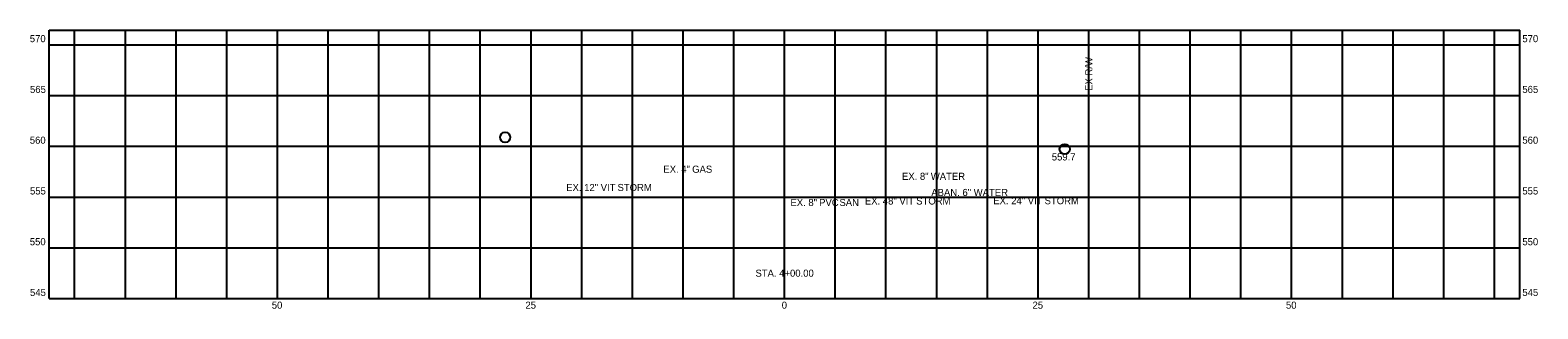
# Model space of a CAD drawing. Extents: x -74 to 74, y 544 to 571.
import ezdxf

# ---------------------------------------------------------------- set-up
doc = ezdxf.new("R2010")
doc.units = 0
for name, color, linetype in [('CM_Corridor_Key_Station', 7, 'Continuous'), ('CM_Corridor_Top_Mesh', 7, 'Continuous'), ('DT_P_Graded_Shoulder', 7, 'Continuous'), ('MD_P_GRADE_BREAK', 7, 'Continuous'), ('MD_P_Surface_Sidewalk', 7, 'Continuous'), ('MD_P_SW_BOT', 7, 'Continuous'), ('MD_P_SW_TOP', 7, 'Continuous'), ('PV_P_Walk', 7, 'Continuous')]:
    doc.layers.add(name, color=color, linetype=linetype)

msp = doc.modelspace()

# ---------------------------------------------------------------- linework, layer by layer
at = {"layer": 'MD_P_GRADE_BREAK'}
for centre in [(-27.55, 560.88), (27.62, 559.72)]:
    msp.add_circle(centre, 0.5, dxfattribs=at)
at = {"layer": 'MD_P_SW_TOP'}
for p, q in [((-72.5, 571.43), (72.5, 571.43)), ((-72.5, 545), (-72.5, 571.43)), ((-70, 545), (-70, 571.43)), ((-65, 545), (-65, 571.43)), ((-60, 545), (-60, 571.43)), ((-55, 545), (-55, 571.43)), ((-50, 545), (-50, 571.43)), ((-45, 545), (-45, 571.43)), ((-40, 545), (-40, 571.43)), ((-35, 545), (-35, 571.43)), ((-30, 545), (-30, 571.43)), ((-25, 545), (-25, 571.43)), ((-20, 545), (-20, 571.43)), ((-15, 545), (-15, 571.43)), ((-10, 545), (-10, 571.43)), ((-5, 545), (-5, 571.43)), ((0, 545), (0, 571.43)), ((5, 545), (5, 571.43)), ((10, 545), (10, 571.43)), ((15, 545), (15, 571.43)), ((20, 545), (20, 571.43)), ((25, 545), (25, 571.43)), ((30, 545), (30, 571.43)), ((35, 545), (35, 571.43)), ((40, 545), (40, 571.43)), ((45, 545), (45, 571.43)), ((50, 545), (50, 571.43)), ((55, 545), (55, 571.43)), ((60, 545), (60, 571.43)), ((65, 545), (65, 571.43)), ((70, 545), (70, 571.43)), ((72.5, 545), (72.5, 571.43)), ((-72.5, 570), (72.5, 570)), ((-72.5, 565), (72.5, 565)), ((-72.5, 560), (72.5, 560)), ((-72.5, 555), (72.5, 555)), ((-72.5, 550), (72.5, 550)), ((-72.5, 545), (72.5, 545))]:
    msp.add_line(p, q, dxfattribs=at)
at = {"layer": 'PV_P_Walk'}
msp.add_line((30, 560.1), (30, 565.1), dxfattribs=at)

# ---------------------------------------------------------------- texts
at = {"layer": 'CM_Corridor_Key_Station'}
for s, p in [('EX. 8"', (0.58, 554.11)), ('PVC', (3.41, 554.11)), ('SAN', (5.41, 554.11))]:
    msp.add_text(s, height=0.7, dxfattribs=at).set_placement(p)
at = {"layer": 'CM_Corridor_Top_Mesh'}
for s, p in [('EX. 4"', (-11.95, 557.39)), ('GAS', (-9.11, 557.39))]:
    msp.add_text(s, height=0.7, dxfattribs=at).set_placement(p)
at = {"layer": 'DT_P_Graded_Shoulder'}
for s, p in [('EX. 12"', (-21.53, 555.59)), ('VIT', (-18.13, 555.59)), ('STORM', (-16.47, 555.59)), ('EX. 48"', (7.92, 554.26)), ('VIT', (11.32, 554.26)), ('STORM', (12.98, 554.26)), ('EX. 24"', (20.58, 554.29)), ('VIT', (23.98, 554.29)), ('STORM', (25.64, 554.29))]:
    msp.add_text(s, height=0.7, dxfattribs=at).set_placement(p)
at = {"layer": 'MD_P_Surface_Sidewalk'}
for s, p in [('EX. 8" ', (11.58, 556.69)), ('WATER', (14.42, 556.69)), ('ABAN. 6" WATER', (14.47, 555.1))]:
    msp.add_text(s, height=0.7, dxfattribs=at).set_placement(p)
at = {"layer": 'MD_P_SW_BOT'}
for s, p in [('570', (-74.42, 570.25)), ('570', (72.75, 570.25)), ('565', (-74.4, 565.25)), ('565', (72.75, 565.25)), ('560', (-74.42, 560.25)), ('560', (72.75, 560.25)), ('559.7', (26.35, 558.6)), ('555', (-74.4, 555.25)), ('555', (72.75, 555.25)), ('550', (-74.42, 550.25)), ('550', (72.75, 550.25)), ('STA. 4+00.00', (-2.87, 547.15)), ('545', (-74.4, 545.25)), ('545', (72.75, 545.25)), ('50', (-50.56, 544)), ('25', (-25.55, 544)), ('0', (-0.28, 544)), ('25', (24.45, 544)), ('50', (49.44, 544))]:
    msp.add_text(s, height=0.7, dxfattribs=at).set_placement(p)
at = {"layer": 'PV_P_Walk'}
msp.add_text('EX R/W', height=0.7, rotation=90, dxfattribs=at).set_placement((30.35, 565.45))

doc.saveas('drawing.dxf')
